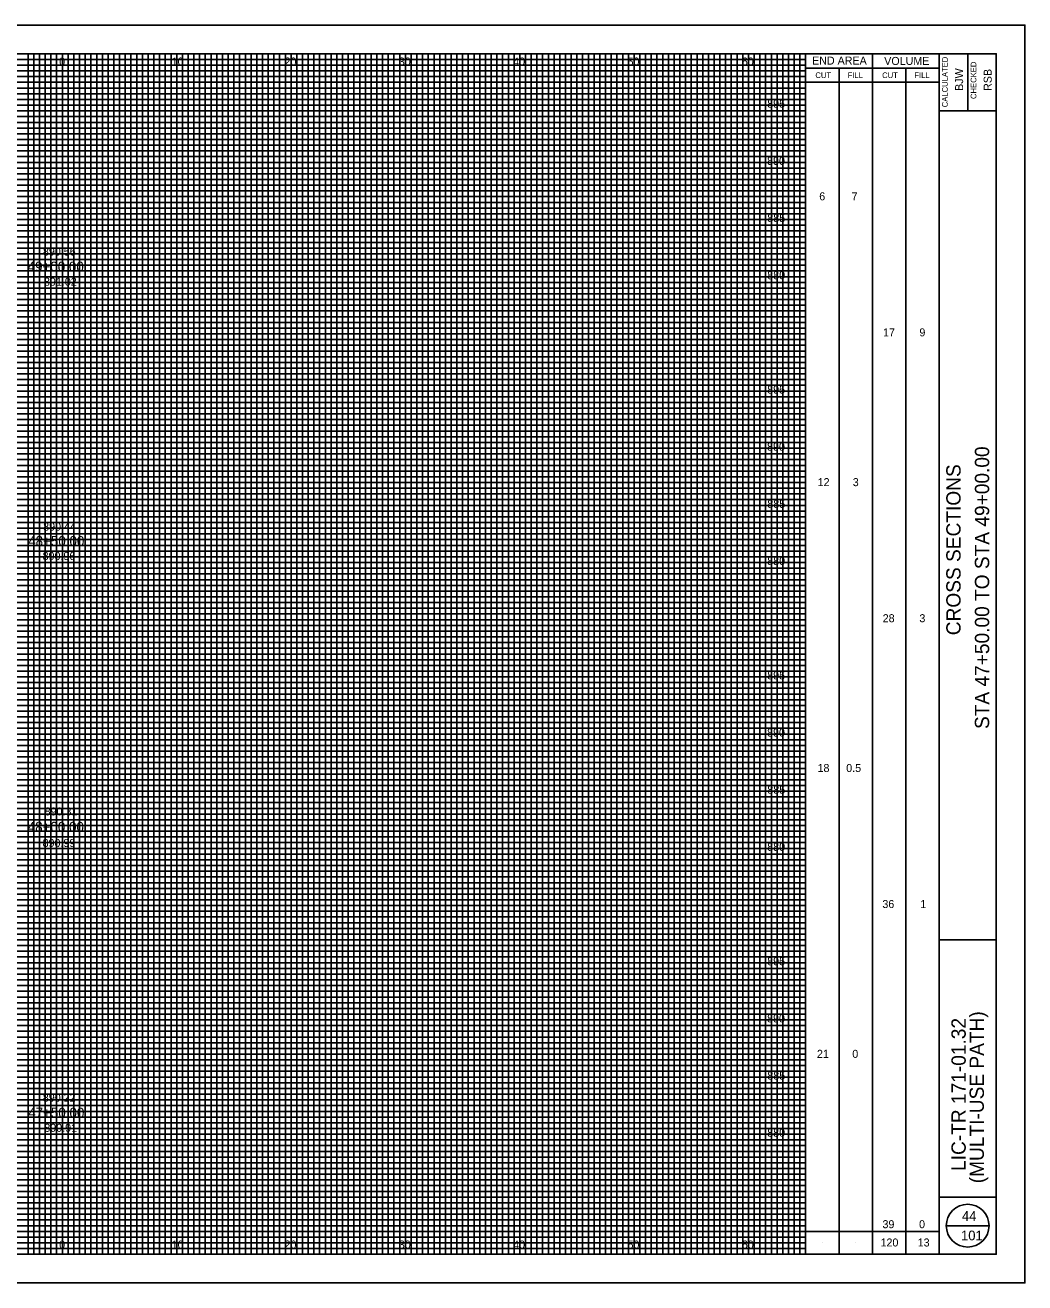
# Model space of a CAD drawing. Extents: x -10 to 160, y -2 to 2522.
# Drawn here: x 72.6 to 160, y 1837.5 to 1947.5 of the extents above; entities that cross this region are included whole.
import ezdxf

# ---------------------------------------------------------------- set-up
doc = ezdxf.new("R2010")
doc.units = 0
for name, color, linetype in [('GK_Cells', 7, 'Continuous'), ('GK_Patterns', 7, 'Continuous'), ('TX_P_10', 7, 'Continuous'), ('TX_X_10', 7, 'Continuous'), ('XS_P_Finished_Grade_Seeded', 7, 'Continuous'), ('XS_P_Pavt_Surface', 7, 'Continuous'), ('XS_P_Subgrade', 7, 'Continuous'), ('XS_X_Ground_Line', 7, 'Continuous')]:
    doc.layers.add(name, color=color, linetype=linetype)

msp = doc.modelspace()

# ---------------------------------------------------------------- linework, layer by layer
at = {"layer": 'GK_Cells'}
msp.add_lwpolyline([(-10, 1837.5), (160, 1837.5), (160, 1947.5), (-10, 1947.5)], close=True, dxfattribs=at)
at = {"layer": 'TX_P_10'}
for p, q in [((140.83, 1840), (140.83, 1945)), ((146.67, 1840), (146.67, 1945)), ((140.83, 1943.75), (152.5, 1943.75)), ((143.75, 1840), (143.75, 1943.75)), ((149.58, 1840), (149.58, 1943.75)), ((140.83, 1942.5), (152.5, 1942.5)), ((140.83, 1842), (152.5, 1842)), ((153.12, 1842.5), (156.88, 1842.5)), ((142.29, 1841), (142.29, 1841)), ((145.21, 1841), (145.21, 1841)), ((148.12, 1841), (148.12, 1841)), ((151.04, 1841), (151.04, 1841))]:
    msp.add_line(p, q, dxfattribs=at)
msp.add_circle((155, 1842.5), 1.87, dxfattribs=at)
at = {"layer": 'TX_X_10'}
for p, q in [((75.83, 1840), (75.83, 1945)), ((80.83, 1840), (80.83, 1945)), ((85.83, 1840), (85.83, 1945)), ((90.83, 1840), (90.83, 1945)), ((95.83, 1840), (95.83, 1945)), ((100.83, 1840), (100.83, 1945)), ((105.83, 1840), (105.83, 1945)), ((110.83, 1840), (110.83, 1945)), ((115.83, 1840), (115.83, 1945)), ((120.83, 1840), (120.83, 1945)), ((125.83, 1840), (125.83, 1945)), ((130.83, 1840), (130.83, 1945)), ((135.83, 1840), (135.83, 1945)), ((5.83, 1940), (140.83, 1940)), ((5.83, 1935), (140.83, 1935)), ((5.83, 1930), (140.83, 1930)), ((5.83, 1925), (140.83, 1925)), ((5.83, 1920), (140.83, 1920)), ((5.83, 1915), (140.83, 1915)), ((5.83, 1910), (140.83, 1910)), ((5.83, 1905), (140.83, 1905)), ((5.83, 1900), (140.83, 1900)), ((5.83, 1895), (140.83, 1895)), ((5.83, 1890), (140.83, 1890)), ((5.83, 1885), (140.83, 1885)), ((5.83, 1880), (140.83, 1880)), ((5.83, 1875), (140.83, 1875)), ((5.83, 1870), (140.83, 1870)), ((5.83, 1865), (140.83, 1865)), ((5.83, 1860), (140.83, 1860)), ((5.83, 1855), (140.83, 1855)), ((5.83, 1850), (140.83, 1850)), ((5.83, 1845), (140.83, 1845))]:
    msp.add_line(p, q, dxfattribs=at)
at = {"layer": 'XS_P_Pavt_Surface'}
for p, q in [((152.5, 1840), (152.5, 1945)), ((155, 1945), (155, 1940)), ((152.5, 1940), (157.5, 1940)), ((152.5, 1867.5), (157.5, 1867.5)), ((152.5, 1845), (157.5, 1845))]:
    msp.add_line(p, q, dxfattribs=at)
msp.add_lwpolyline([(0, 1945), (157.5, 1945), (157.5, 1840), (0, 1840)], close=True, dxfattribs=at)
at = {"layer": 'XS_X_Ground_Line'}
for p, q in [((72.83, 1840), (72.83, 1945)), ((73.33, 1840), (73.33, 1945)), ((73.83, 1840), (73.83, 1945)), ((74.33, 1840), (74.33, 1945)), ((74.83, 1840), (74.83, 1945)), ((75.33, 1840), (75.33, 1945)), ((76.33, 1840), (76.33, 1945)), ((76.83, 1840), (76.83, 1945)), ((77.33, 1840), (77.33, 1945)), ((77.83, 1840), (77.83, 1945)), ((78.33, 1840), (78.33, 1945)), ((78.83, 1840), (78.83, 1945)), ((79.33, 1840), (79.33, 1945)), ((79.83, 1840), (79.83, 1945)), ((80.33, 1840), (80.33, 1945)), ((81.33, 1840), (81.33, 1945)), ((81.83, 1840), (81.83, 1945)), ((82.33, 1840), (82.33, 1945)), ((82.83, 1840), (82.83, 1945)), ((83.33, 1840), (83.33, 1945)), ((83.83, 1840), (83.83, 1945)), ((84.33, 1840), (84.33, 1945)), ((84.83, 1840), (84.83, 1945)), ((85.33, 1840), (85.33, 1945)), ((86.33, 1840), (86.33, 1945)), ((86.83, 1840), (86.83, 1945)), ((87.33, 1840), (87.33, 1945)), ((87.83, 1840), (87.83, 1945)), ((88.33, 1840), (88.33, 1945)), ((88.83, 1840), (88.83, 1945)), ((89.33, 1840), (89.33, 1945)), ((89.83, 1840), (89.83, 1945)), ((90.33, 1840), (90.33, 1945)), ((91.33, 1840), (91.33, 1945)), ((91.83, 1840), (91.83, 1945)), ((92.33, 1840), (92.33, 1945)), ((92.83, 1840), (92.83, 1945)), ((93.33, 1840), (93.33, 1945)), ((93.83, 1840), (93.83, 1945)), ((94.33, 1840), (94.33, 1945)), ((94.83, 1840), (94.83, 1945)), ((95.33, 1840), (95.33, 1945)), ((96.33, 1840), (96.33, 1945)), ((96.83, 1840), (96.83, 1945)), ((97.33, 1840), (97.33, 1945)), ((97.83, 1840), (97.83, 1945)), ((98.33, 1840), (98.33, 1945)), ((98.83, 1840), (98.83, 1945)), ((99.33, 1840), (99.33, 1945)), ((99.83, 1840), (99.83, 1945)), ((100.33, 1840), (100.33, 1945)), ((101.33, 1840), (101.33, 1945)), ((101.83, 1840), (101.83, 1945)), ((102.33, 1840), (102.33, 1945)), ((102.83, 1840), (102.83, 1945)), ((103.33, 1840), (103.33, 1945)), ((103.83, 1840), (103.83, 1945)), ((104.33, 1840), (104.33, 1945)), ((104.83, 1840), (104.83, 1945)), ((105.33, 1840), (105.33, 1945)), ((106.33, 1840), (106.33, 1945)), ((106.83, 1840), (106.83, 1945)), ((107.33, 1840), (107.33, 1945)), ((107.83, 1840), (107.83, 1945)), ((108.33, 1840), (108.33, 1945)), ((108.83, 1840), (108.83, 1945)), ((109.33, 1840), (109.33, 1945)), ((109.83, 1840), (109.83, 1945)), ((110.33, 1840), (110.33, 1945)), ((111.33, 1840), (111.33, 1945)), ((111.83, 1840), (111.83, 1945)), ((112.33, 1840), (112.33, 1945)), ((112.83, 1840), (112.83, 1945)), ((113.33, 1840), (113.33, 1945)), ((113.83, 1840), (113.83, 1945)), ((114.33, 1840), (114.33, 1945)), ((114.83, 1840), (114.83, 1945)), ((115.33, 1840), (115.33, 1945)), ((116.33, 1840), (116.33, 1945)), ((116.83, 1840), (116.83, 1945)), ((117.33, 1840), (117.33, 1945)), ((117.83, 1840), (117.83, 1945)), ((118.33, 1840), (118.33, 1945)), ((118.83, 1840), (118.83, 1945)), ((119.33, 1840), (119.33, 1945)), ((119.83, 1840), (119.83, 1945)), ((120.33, 1840), (120.33, 1945)), ((121.33, 1840), (121.33, 1945)), ((121.83, 1840), (121.83, 1945)), ((122.33, 1840), (122.33, 1945)), ((122.83, 1840), (122.83, 1945)), ((123.33, 1840), (123.33, 1945)), ((123.83, 1840), (123.83, 1945)), ((124.33, 1840), (124.33, 1945)), ((124.83, 1840), (124.83, 1945)), ((125.33, 1840), (125.33, 1945)), ((126.33, 1840), (126.33, 1945)), ((126.83, 1840), (126.83, 1945)), ((127.33, 1840), (127.33, 1945)), ((127.83, 1840), (127.83, 1945)), ((128.33, 1840), (128.33, 1945)), ((128.83, 1840), (128.83, 1945)), ((129.33, 1840), (129.33, 1945)), ((129.83, 1840), (129.83, 1945)), ((130.33, 1840), (130.33, 1945)), ((131.33, 1840), (131.33, 1945)), ((131.83, 1840), (131.83, 1945)), ((132.33, 1840), (132.33, 1945)), ((132.83, 1840), (132.83, 1945)), ((133.33, 1840), (133.33, 1945)), ((133.83, 1840), (133.83, 1945)), ((134.33, 1840), (134.33, 1945)), ((134.83, 1840), (134.83, 1945)), ((135.33, 1840), (135.33, 1945)), ((136.33, 1840), (136.33, 1945)), ((136.83, 1840), (136.83, 1945)), ((137.33, 1840), (137.33, 1945)), ((137.83, 1840), (137.83, 1945)), ((138.33, 1840), (138.33, 1945)), ((138.83, 1840), (138.83, 1945)), ((139.33, 1840), (139.33, 1945)), ((139.83, 1840), (139.83, 1945)), ((140.33, 1840), (140.33, 1945)), ((5.83, 1944.5), (140.83, 1944.5)), ((5.83, 1944), (140.83, 1944)), ((5.83, 1943.5), (140.83, 1943.5)), ((5.83, 1943), (140.83, 1943)), ((5.83, 1942.5), (140.83, 1942.5)), ((5.83, 1942), (140.83, 1942)), ((5.83, 1941.5), (140.83, 1941.5)), ((5.83, 1941), (140.83, 1941)), ((5.83, 1940.5), (140.83, 1940.5)), ((5.83, 1939.5), (140.83, 1939.5)), ((5.83, 1939), (140.83, 1939)), ((5.83, 1938.5), (140.83, 1938.5)), ((5.83, 1938), (140.83, 1938)), ((5.83, 1937.5), (140.83, 1937.5)), ((5.83, 1937), (140.83, 1937)), ((5.83, 1936.5), (140.83, 1936.5)), ((5.83, 1936), (140.83, 1936)), ((5.83, 1935.5), (140.83, 1935.5)), ((5.83, 1934.5), (140.83, 1934.5)), ((5.83, 1934), (140.83, 1934)), ((5.83, 1933.5), (140.83, 1933.5)), ((5.83, 1933), (140.83, 1933)), ((5.83, 1932.5), (140.83, 1932.5)), ((5.83, 1932), (140.83, 1932)), ((5.83, 1931.5), (140.83, 1931.5)), ((5.83, 1931), (140.83, 1931)), ((5.83, 1930.5), (140.83, 1930.5)), ((5.83, 1929.5), (140.83, 1929.5)), ((5.83, 1929), (140.83, 1929)), ((5.83, 1928.5), (140.83, 1928.5)), ((5.83, 1928), (140.83, 1928)), ((5.83, 1927.5), (140.83, 1927.5)), ((5.83, 1927), (140.83, 1927)), ((5.83, 1926.5), (140.83, 1926.5)), ((5.83, 1926), (140.83, 1926)), ((5.83, 1925.5), (140.83, 1925.5)), ((5.83, 1924.5), (140.83, 1924.5)), ((5.83, 1924), (140.83, 1924)), ((5.83, 1923.5), (140.83, 1923.5)), ((5.83, 1923), (140.83, 1923)), ((5.83, 1922.5), (140.83, 1922.5)), ((5.83, 1922), (140.83, 1922)), ((5.83, 1921.5), (140.83, 1921.5)), ((5.83, 1921), (140.83, 1921)), ((5.83, 1920.5), (140.83, 1920.5)), ((5.83, 1919.5), (140.83, 1919.5)), ((5.83, 1919), (140.83, 1919)), ((5.83, 1918.5), (140.83, 1918.5)), ((5.83, 1918), (140.83, 1918)), ((5.83, 1917.5), (140.83, 1917.5)), ((5.83, 1917), (140.83, 1917)), ((5.83, 1916.5), (140.83, 1916.5)), ((5.83, 1916), (140.83, 1916)), ((5.83, 1915.5), (140.83, 1915.5)), ((5.83, 1914.5), (140.83, 1914.5)), ((5.83, 1914), (140.83, 1914)), ((5.83, 1913.5), (140.83, 1913.5)), ((5.83, 1913), (140.83, 1913)), ((5.83, 1912.5), (140.83, 1912.5)), ((5.83, 1912), (140.83, 1912)), ((5.83, 1911.5), (140.83, 1911.5)), ((5.83, 1911), (140.83, 1911)), ((5.83, 1910.5), (140.83, 1910.5)), ((5.83, 1909.5), (140.83, 1909.5)), ((5.83, 1909), (140.83, 1909)), ((5.83, 1908.5), (140.83, 1908.5)), ((5.83, 1908), (140.83, 1908)), ((5.83, 1907.5), (140.83, 1907.5)), ((5.83, 1907), (140.83, 1907)), ((5.83, 1906.5), (140.83, 1906.5)), ((5.83, 1906), (140.83, 1906)), ((5.83, 1905.5), (140.83, 1905.5)), ((5.83, 1904.5), (140.83, 1904.5)), ((5.83, 1904), (140.83, 1904)), ((5.83, 1903.5), (140.83, 1903.5)), ((5.83, 1903), (140.83, 1903)), ((5.83, 1902.5), (140.83, 1902.5)), ((5.83, 1902), (140.83, 1902)), ((5.83, 1901.5), (140.83, 1901.5)), ((5.83, 1901), (140.83, 1901)), ((5.83, 1900.5), (140.83, 1900.5)), ((5.83, 1899.5), (140.83, 1899.5)), ((5.83, 1899), (140.83, 1899)), ((5.83, 1898.5), (140.83, 1898.5)), ((5.83, 1898), (140.83, 1898)), ((5.83, 1897.5), (140.83, 1897.5)), ((5.83, 1897), (140.83, 1897)), ((5.83, 1896.5), (140.83, 1896.5)), ((5.83, 1896), (140.83, 1896)), ((5.83, 1895.5), (140.83, 1895.5)), ((5.83, 1894.5), (140.83, 1894.5)), ((5.83, 1894), (140.83, 1894)), ((5.83, 1893.5), (140.83, 1893.5)), ((5.83, 1893), (140.83, 1893)), ((5.83, 1892.5), (140.83, 1892.5)), ((5.83, 1892), (140.83, 1892)), ((5.83, 1891.5), (140.83, 1891.5)), ((5.83, 1891), (140.83, 1891)), ((5.83, 1890.5), (140.83, 1890.5)), ((5.83, 1889.5), (140.83, 1889.5)), ((5.83, 1889), (140.83, 1889)), ((5.83, 1888.5), (140.83, 1888.5)), ((5.83, 1888), (140.83, 1888)), ((5.83, 1887.5), (140.83, 1887.5)), ((5.83, 1887), (140.83, 1887)), ((5.83, 1886.5), (140.83, 1886.5)), ((5.83, 1886), (140.83, 1886)), ((5.83, 1885.5), (140.83, 1885.5)), ((5.83, 1884.5), (140.83, 1884.5)), ((5.83, 1884), (140.83, 1884)), ((5.83, 1883.5), (140.83, 1883.5)), ((5.83, 1883), (140.83, 1883)), ((5.83, 1882.5), (140.83, 1882.5)), ((5.83, 1882), (140.83, 1882)), ((5.83, 1881.5), (140.83, 1881.5)), ((5.83, 1881), (140.83, 1881)), ((5.83, 1880.5), (140.83, 1880.5)), ((5.83, 1879.5), (140.83, 1879.5)), ((5.83, 1879), (140.83, 1879)), ((5.83, 1878.5), (140.83, 1878.5)), ((5.83, 1878), (140.83, 1878)), ((5.83, 1877.5), (140.83, 1877.5)), ((5.83, 1877), (140.83, 1877)), ((5.83, 1876.5), (140.83, 1876.5)), ((5.83, 1876), (140.83, 1876)), ((5.83, 1875.5), (140.83, 1875.5)), ((5.83, 1874.5), (140.83, 1874.5)), ((5.83, 1874), (140.83, 1874)), ((5.83, 1873.5), (140.83, 1873.5)), ((5.83, 1873), (140.83, 1873)), ((5.83, 1872.5), (140.83, 1872.5)), ((5.83, 1872), (140.83, 1872)), ((5.83, 1871.5), (140.83, 1871.5)), ((5.83, 1871), (140.83, 1871)), ((5.83, 1870.5), (140.83, 1870.5)), ((5.83, 1869.5), (140.83, 1869.5)), ((5.83, 1869), (140.83, 1869)), ((5.83, 1868.5), (140.83, 1868.5)), ((5.83, 1868), (140.83, 1868)), ((5.83, 1867.5), (140.83, 1867.5)), ((5.83, 1867), (140.83, 1867)), ((5.83, 1866.5), (140.83, 1866.5)), ((5.83, 1866), (140.83, 1866)), ((5.83, 1865.5), (140.83, 1865.5)), ((5.83, 1864.5), (140.83, 1864.5)), ((5.83, 1864), (140.83, 1864)), ((5.83, 1863.5), (140.83, 1863.5)), ((5.83, 1863), (140.83, 1863)), ((5.83, 1862.5), (140.83, 1862.5)), ((5.83, 1862), (140.83, 1862)), ((5.83, 1861.5), (140.83, 1861.5)), ((5.83, 1861), (140.83, 1861)), ((5.83, 1860.5), (140.83, 1860.5)), ((5.83, 1859.5), (140.83, 1859.5)), ((5.83, 1859), (140.83, 1859)), ((5.83, 1858.5), (140.83, 1858.5)), ((5.83, 1858), (140.83, 1858)), ((5.83, 1857.5), (140.83, 1857.5)), ((5.83, 1857), (140.83, 1857)), ((5.83, 1856.5), (140.83, 1856.5)), ((5.83, 1856), (140.83, 1856)), ((5.83, 1855.5), (140.83, 1855.5)), ((5.83, 1854.5), (140.83, 1854.5)), ((5.83, 1854), (140.83, 1854)), ((5.83, 1853.5), (140.83, 1853.5)), ((5.83, 1853), (140.83, 1853)), ((5.83, 1852.5), (140.83, 1852.5)), ((5.83, 1852), (140.83, 1852)), ((5.83, 1851.5), (140.83, 1851.5)), ((5.83, 1851), (140.83, 1851)), ((5.83, 1850.5), (140.83, 1850.5)), ((5.83, 1849.5), (140.83, 1849.5)), ((5.83, 1849), (140.83, 1849)), ((5.83, 1848.5), (140.83, 1848.5)), ((5.83, 1848), (140.83, 1848)), ((5.83, 1847.5), (140.83, 1847.5)), ((5.83, 1847), (140.83, 1847)), ((5.83, 1846.5), (140.83, 1846.5)), ((5.83, 1846), (140.83, 1846)), ((5.83, 1845.5), (140.83, 1845.5)), ((5.83, 1844.5), (140.83, 1844.5)), ((5.83, 1844), (140.83, 1844)), ((5.83, 1843.5), (140.83, 1843.5)), ((5.83, 1843), (140.83, 1843)), ((5.83, 1842.5), (140.83, 1842.5)), ((5.83, 1842), (140.83, 1842)), ((5.83, 1841.5), (140.83, 1841.5)), ((5.83, 1841), (140.83, 1841)), ((5.83, 1840.5), (140.83, 1840.5))]:
    msp.add_line(p, q, dxfattribs=at)

# ---------------------------------------------------------------- texts
at = {"layer": 'GK_Patterns'}
for s, height, p in [('0', 0.7, (75.55, 1943.97)), ('0', 0.7, (75.55, 1943.97)), ('10', 0.7, (85.39, 1943.97)), ('20', 0.7, (95.26, 1943.97)), ('30', 0.7, (105.25, 1943.97)), ('40', 0.7, (115.25, 1943.97)), ('50', 0.7, (125.25, 1943.97)), ('60', 0.7, (135.25, 1943.97)), ('895', 0.7, (137.47, 1940.28)), ('890', 0.7, (137.46, 1935.28)), ('6', 0.7, (142.02, 1932.18)), ('7', 0.7, (144.85, 1932.18)), ('885', 0.7, (137.48, 1930.28)), ('49+00.00', 0.875, (72.79, 1925.94)), ('880', 0.7, (137.47, 1925.28)), ('17', 0.7, (147.6, 1920.28)), ('9', 0.7, (150.78, 1920.28)), ('895', 0.7, (137.47, 1915.28)), ('890', 0.7, (137.46, 1910.28)), ('12', 0.7, (141.88, 1907.18)), ('3', 0.7, (144.95, 1907.18)), ('885', 0.7, (137.48, 1905.28)), ('48+50.00', 0.875, (72.84, 1901.94)), ('880', 0.7, (137.47, 1900.28)), ('28', 0.7, (147.57, 1895.28)), ('3', 0.7, (150.78, 1895.28)), ('895', 0.7, (137.47, 1890.28)), ('890', 0.7, (137.46, 1885.28)), ('18', 0.7, (141.87, 1882.18)), ('0.5', 0.7, (144.38, 1882.18)), ('885', 0.7, (137.48, 1880.28)), ('48+00.00', 0.875, (72.8, 1876.94)), ('880', 0.7, (137.47, 1875.28)), ('36', 0.7, (147.54, 1870.28)), ('1', 0.7, (150.86, 1870.28)), ('895', 0.7, (137.47, 1865.28)), ('890', 0.7, (137.46, 1860.28)), ('21', 0.7, (141.82, 1857.18)), ('0', 0.7, (144.91, 1857.18)), ('885', 0.7, (137.48, 1855.28)), ('47+50.00', 0.875, (72.84, 1851.94)), ('880', 0.7, (137.47, 1850.28)), ('39', 0.7, (147.55, 1842.28)), ('0', 0.7, (150.75, 1842.28)), ('0', 0.7, (75.55, 1840.5)), ('0', 0.7, (75.55, 1840.5)), ('10', 0.7, (85.39, 1840.5)), ('20', 0.7, (95.26, 1840.5)), ('30', 0.7, (105.25, 1840.5)), ('40', 0.7, (115.25, 1840.5)), ('50', 0.7, (125.25, 1840.5)), ('60', 0.7, (135.25, 1840.5)), ('120', 0.7, (147.38, 1840.68)), ('13', 0.7, (150.63, 1840.68))]:
    msp.add_text(s, height=height, dxfattribs=at).set_placement(p)
at = {"layer": 'TX_P_10'}
for s, height, p in [('END AREA', 0.7, (141.39, 1944.05)), ('VOLUME', 0.7, (147.7, 1944.02)), ('CUT', 0.5, (141.68, 1942.87)), ('FILL', 0.5, (144.5, 1942.87)), ('CUT', 0.5, (147.52, 1942.87)), ('FILL', 0.5, (150.34, 1942.87)), ('44', 0.85, (154.5, 1842.92)), ('101', 0.85, (154.42, 1841.22))]:
    msp.add_text(s, height=height, dxfattribs=at).set_placement(p)
for s, height, p in [('CALCULATED', 0.5, (153.26, 1940.32)), ('BJW', 0.7, (154.6, 1941.75)), ('CHECKED', 0.5, (155.76, 1941.04)), ('RSB', 0.7, (157.1, 1941.75)), ('STA 47+50.00 TO STA 49+00.00', 1.25, (156.88, 1885.94)), ('CROSS SECTIONS', 1.25, (154.38, 1894.14)), ('LIC-TR 171-01.32', 1.25, (154.83, 1847.29)), ('(MULTI-USE PATH)', 1.25, (156.42, 1846.21))]:
    msp.add_text(s, height=height, rotation=90, dxfattribs=at).set_placement(p)
at = {"layer": 'XS_P_Finished_Grade_Seeded'}
for s, p in [('891.02', (74.22, 1924.71)), ('890.96', (74.1, 1900.72)), ('890.99', (74.1, 1875.62)), ('890.91', (74.25, 1850.71))]:
    msp.add_text(s, height=0.7, dxfattribs=at).set_placement(p)
at = {"layer": 'XS_P_Subgrade'}
for s, p in [('890.56', (74.13, 1927.35)), ('890.44', (74.15, 1903.29)), ('890.31', (74.28, 1878.38)), ('890.22', (74.12, 1853.35))]:
    msp.add_text(s, height=0.7, dxfattribs=at).set_placement(p)

doc.saveas('drawing.dxf')
